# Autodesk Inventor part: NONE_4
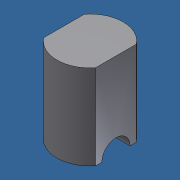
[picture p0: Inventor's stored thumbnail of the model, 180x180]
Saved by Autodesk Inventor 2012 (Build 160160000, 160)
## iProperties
Created: 2013-10
Part Number: NONE_4
Material: Default
Document SubType Name: Modeling
Designer: Admin
Density: 1 g/cm^3
Author: Admin
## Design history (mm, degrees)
node "Sankq_7011P566_Handle1"
node "Base1"
body "Solid1"
